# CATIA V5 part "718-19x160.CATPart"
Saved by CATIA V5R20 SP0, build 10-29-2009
Part number: 718-19x160
Definition: NONE
Nomenclature: 718-19x160
Source: Unknown
Description: 718-19x160
Bounding box of the stored display mesh (mm): x 0 to 183, y -12.5 to 12.5, z -12.5 to 12.5
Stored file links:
  C:\Users\Utente\Desktop\IO LAVORO\3D X SITO CF\X SITO\718\718-19x160.CATPart

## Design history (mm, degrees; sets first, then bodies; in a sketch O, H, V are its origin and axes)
Body1 "718-19x160" (main body)
  Solid1: solid without history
